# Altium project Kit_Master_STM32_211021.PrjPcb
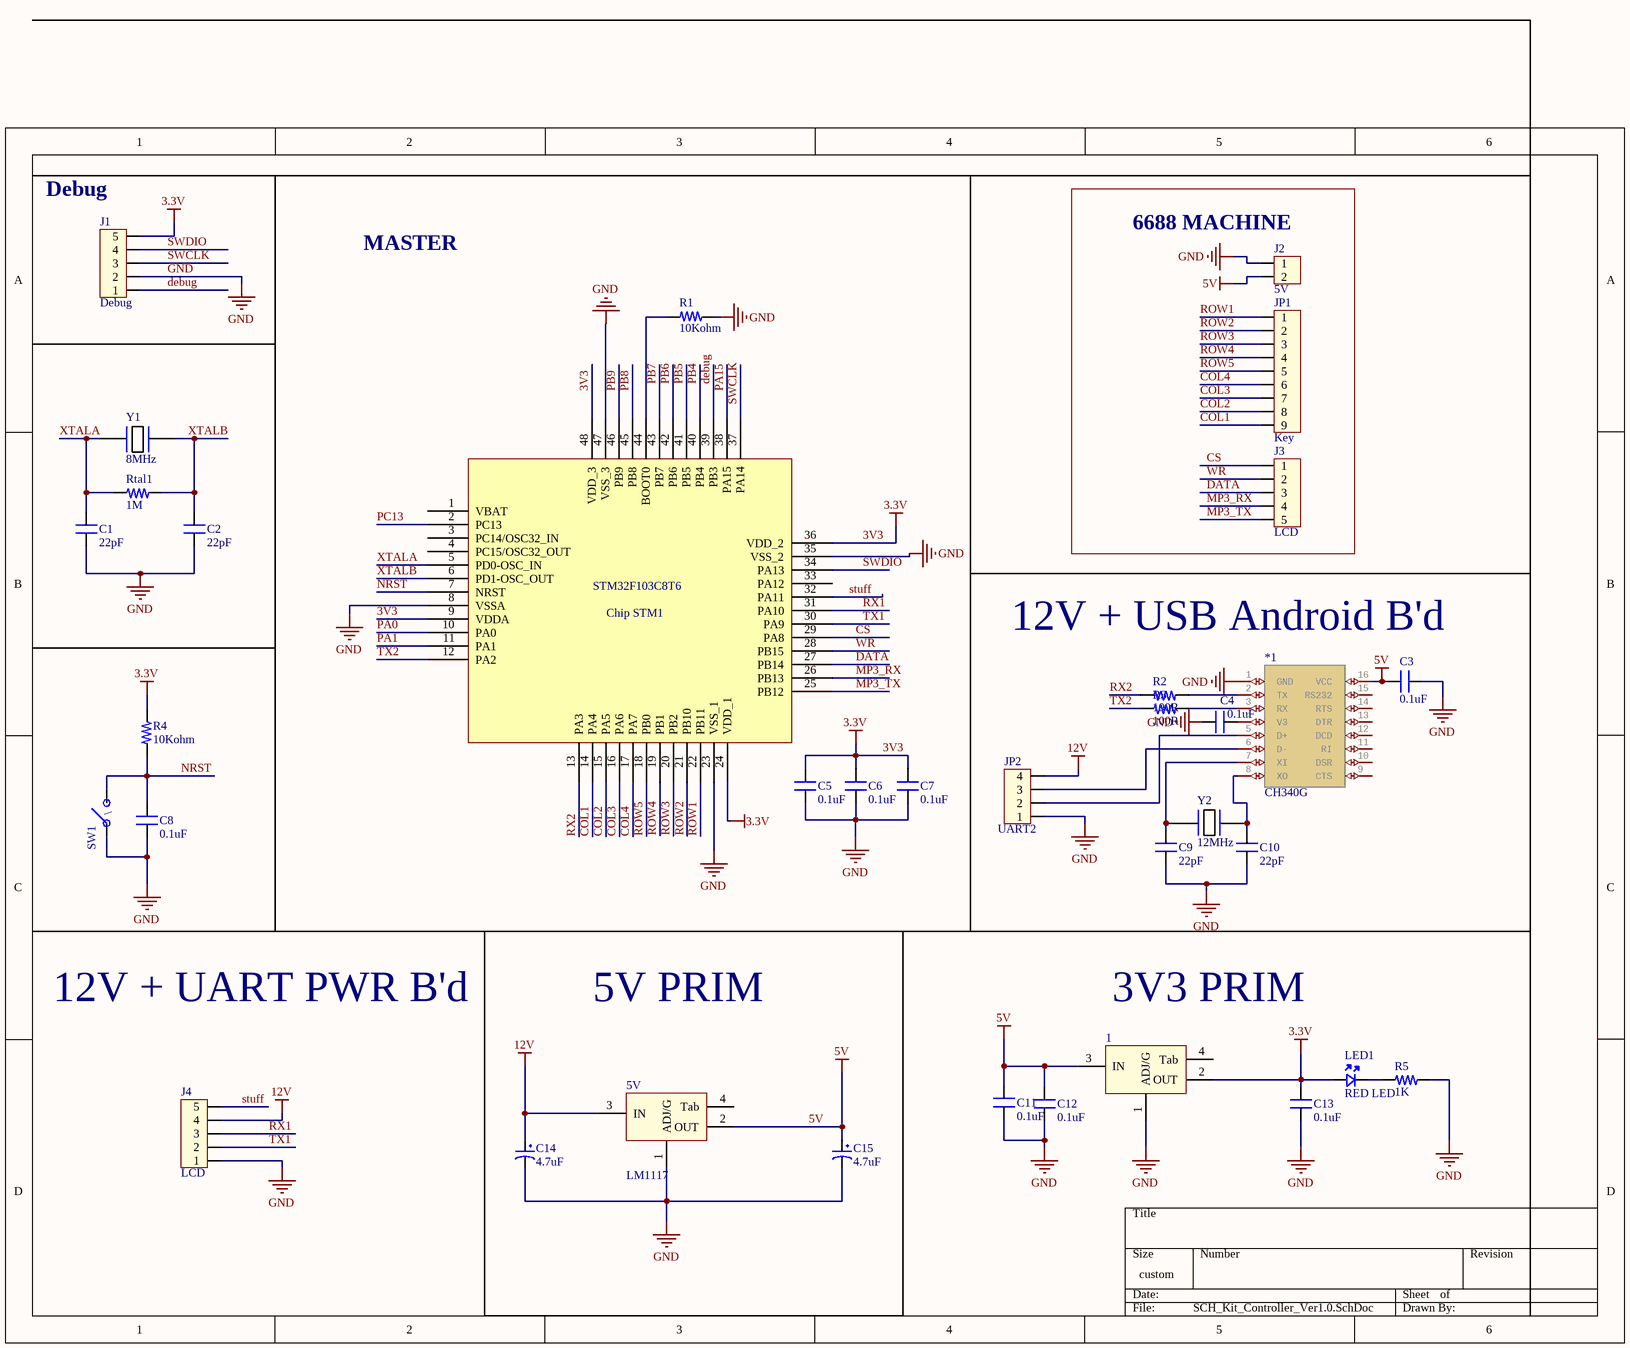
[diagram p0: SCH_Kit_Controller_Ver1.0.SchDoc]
1 sheet, 35 parts. Net scope: global (net labels, ports and power ports of the same name join across sheets).

## Sheet SCH_Kit_Controller_Ver1.0.SchDoc
size 304 x 228 mm; SheetNumber: 1; SheetTotal: 1

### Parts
1  (no value)  [SOT223-4N]
5V  LM1117  [SOT223-4N]
*1  CH340G  [CH340G]
C1  22pF  [CAP_0805]
C2  22pF  [CAP_0805]
C3  0.1uF  [CAP_0805]
C4  0.1uF  [CAP_0805]
C5  0.1uF  [CAP_0805]
C6  0.1uF  [CAP_0805]
C7  0.1uF  [CAP_0805]
C8  0.1uF  [CAP_0805]
C9  22pF  [CAP_0805]
C10  22pF  [CAP_0805]
C11  0.1uF  [CAP_0805]
C12  0.1uF  [CAP_0805]
C13  0.1uF  [CAP_0805]
C14  4.7uF  [tu hoa 8mm]
C15  4.7uF  [tu hoa 8mm]
Chip_STM1  STM32F103C8T6  [LQFP-48_19.6_393_58X11_SMD]
J1  Debug  [CON5]
J2  5V  [CON2]
J3  LCD  [CON5]
J4  LCD  [CON5]
JP1  Key  [CON9]
JP2  UART2  [CON4]
LED1  RED LED  [LED_0805]
R1  10Kohm  [RES_0805]
R2  100R  [RES_0805]
R3  100R  [RES_0805]
R4  10Kohm  [RES_0805]
R5  1K  [RES_0805]
Rtal1  1M  [RES_0805]
SW1  \  [SW_342_SMD]
Y1  8MHz  [XTAL_314_240X47_SMD]
Y2  12MHz  [XTAL_314_240X47_SMD]

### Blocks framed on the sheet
6688 MACHINE: J2 J3 JP1

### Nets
3V3: 1.2(OUT) C5.2 C6.2 C7.2 C13.2 Chip_STM1.9(VDDA) Chip_STM1.24(VDD_1) Chip_STM1.36(VDD_2) Chip_STM1.48(VDD_3) J1.5 LED1.A R4.2  [also labelled 3.3V]
5V: 1.3(IN) 5V.2(OUT) *1.16(VCC) C3.2 C11.2 C12.2 C15.1 J2.2
12V: 5V.3(IN) C14.1 J4.4 JP2.4
GND: 1.1(ADJ/G) 5V.1(ADJ/G) *1.1(GND) C1.1 C2.1 C3.1 C4.2 C5.1 C6.1 C7.1 C8.1 C9.1 C10.1 C11.1 C12.1 C13.1 C14.2 C15.2 Chip_STM1.8(VSSA) Chip_STM1.23(VSS_1) Chip_STM1.35(VSS_2) Chip_STM1.47(VSS_3) J1.2 J2.1 J4.1 JP2.1 R1.2 R5.1 SW1.1
COL1: Chip_STM1.14(PA4) JP1.9
COL2: Chip_STM1.15(PA5) JP1.8
COL3: Chip_STM1.16(PA6) JP1.7
COL4: Chip_STM1.17(PA7) JP1.6
CS: Chip_STM1.29(PA8) J3.1
DATA: Chip_STM1.27(PB14) J3.3
debug: Chip_STM1.39(PB3) J1.1
MP3_RX: Chip_STM1.26(PB13) J3.4
MP3_TX: Chip_STM1.25(PB12) J3.5
NRST: C8.2 Chip_STM1.7(NRST) R4.1 SW1.2
PA0: Chip_STM1.10(PA0)
PA1: Chip_STM1.11(PA1)
PA15: Chip_STM1.38(PA15)
PB4: Chip_STM1.40(PB4)
PB5: Chip_STM1.41(PB5)
PB6: Chip_STM1.42(PB6)
PB7: Chip_STM1.43(PB7)
PB8: Chip_STM1.45(PB8)
PB9: Chip_STM1.46(PB9)
PC13: Chip_STM1.2(PC13)
ROW1: Chip_STM1.22(PB11) JP1.1
ROW2: Chip_STM1.21(PB10) JP1.2
ROW3: Chip_STM1.20(PB2) JP1.3
ROW4: Chip_STM1.19(PB1) JP1.4
ROW5: Chip_STM1.18(PB0) JP1.5
RX1: Chip_STM1.31(PA10) J4.3
RX2: Chip_STM1.13(PA3) R2.2
stuff: Chip_STM1.32(PA11) J4.5
SWCLK: Chip_STM1.37(PA14) J1.3
SWDIO: Chip_STM1.34(PA13) J1.4
TX1: Chip_STM1.30(PA9) J4.2
TX2: Chip_STM1.12(PA2) R3.2
WR: Chip_STM1.28(PB15) J3.2
XTALA: C1.2 Chip_STM1.5(PD0-OSC_IN) Rtal1.2 Y1.1
XTALB: C2.2 Chip_STM1.6(PD1-OSC_OUT) Rtal1.1 Y1.2
Net*1_2: *1.2(TX) R2.1
Net*1_3: *1.3(RX) R3.1
Net*1_4: *1.4(V3) C4.1
Net*1_5: *1.5(D+) JP2.2
Net*1_6: *1.6(D-) JP2.3
Net*1_7: *1.7(XI) C9.2 Y2.2
Net*1_8: *1.8(XO) C10.2 Y2.1
NetChip_STM1_44: Chip_STM1.44(BOOT0) R1.1
NetLED1_K: LED1.K R5.2

Not connected (* = marked no-connect by the designer): 1 4(Tab); 5V 4(Tab); *1 9(CTS) 10(DSR) 11(RI) 12(DCD) 13(DTR) 14(RTS) 15(RS232); Chip_STM1 1(VBAT) 3(PC14/OSC32_IN) 4(PC15/OSC32_OUT) 33(PA12)

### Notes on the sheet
- (near J1) Debug
- MASTER
- 12V + USB Android B'd
- 12V + UART PWR B'd
- 5V PRIM
- (near 1) 3V3 PRIM

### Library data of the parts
1 5V = LM1117: 3v3; Value: LM317
C1 C2 C9 C10 = CAP_22pF-50V-5%-0805: 22pF ±5% 50V Ceramic Capacitor C0G, NP0 0805 (2012 Metric); Manufacturer: KEMET; Manufacturer Part Number: C0805C220J5GACTU
C3-C8 C11-C13 = CAP_0.1uF-50V-5%-0805: 0.1µF ±5% 50V Ceramic Capacitor X7R 0805 (2012 Metric); Manufacturer: KEMET; Manufacturing Part Number: C0805C104J5RACTU
C14 C15 = Tu Hoa 4.7uF 400V 8x12: Cắm; Don_Vi: Con; So_Chan: 2; Ten_Linh_Kien: Tụ Hóa 4.7uF 400V 8x12MM; Ma_Hang: MH003744
Chip_STM1 = IC-STM32F103C8T6 _1: ARM® Cortex®-M3 STM32F1 Microcontroller IC 32-Bit 72MHz 64KB (64K x 8) FLASH; Manufacturer: STMicroelectronics
J1 J3 J4 = Con5: Connector 5
J2 = Con2: Connector 2
JP1 = Con9: Connector 9
JP2 = Con4: Connector 4
LED1 = LED-RED_10mA-0805: Red 621nm LED Indication - Discrete 2V 0805 (2012 Metric); Manufacturer: Lite-On Inc.; Manufacturer Part Number: LTST-C170EKT
R1 = RES_10K-0.125W-1%-0805: 10 kOhms ±1% 0.125W, 1/8W Chip Resistor 0805 (2012 Metric) Moisture Resistant Thick Film; Manufacturer: Yageo; Manufacturing Part Number: RC0805FR-0710KL
R2 R3 = RES_0ohm-0.125W-1%-0805_1: 1000Ohms ±1% 0.125W, 1/8W Chip Resistor 0805 (2012 Metric) Moisture Resistant Thick Film; Manufacturer: 垈㎵á; Manufacturer Part Number: RC0805FR-071KL
R4 Rtal1 = RES_10MOHM-0.125W-1%-0805: 10 MOhms ±1% 0.125W, 1/8W Chip Resistor 0805 (2012 Metric) Automotive AEC-Q200, High Voltage Thick Film; Manufacturer: Rohm Semiconductor; Manufacturing Part Number: KTR10EZPF1005
R5 = RES_1K-0.125W-1%-0805: 1 kOhms ±1% 0.125W, 1/8W Chip Resistor 0805 (2012 Metric) Moisture Resistant Thick Film; Manufacturer: 垈㎵á; Manufacturer Part Number: RC0805FR-071KL
SW1 = SW_KSR223GLFG-SMD: Tactile Switch SPST-NO Top Actuated Surface Mount; Manufacturer: C&K
Y1 Y2 = XTAL_8MHZ-LFXTAL030234: Crystals 8MHz 22pF -20C 70C; Manufacturer: IQD Frequency Products; Manufacturing Part Number: LFXTAL030234Reel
